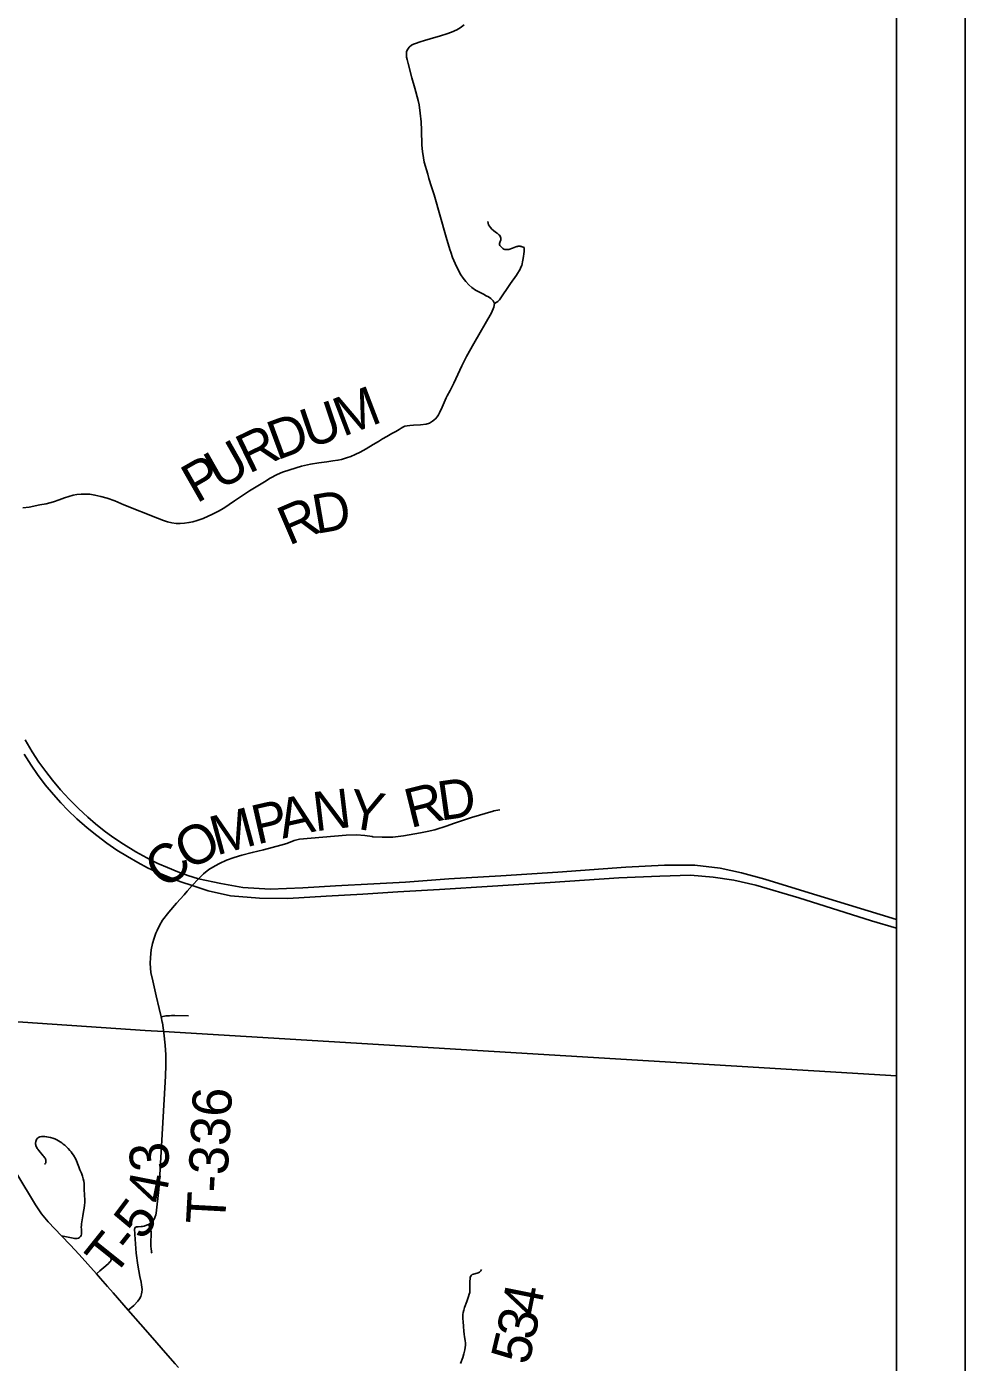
# Model space of a CAD drawing. Extents: x 0 to 34, y 0 to 22.
# Drawn here: x 7.513 to 8.876, y 18.32 to 20.26 of the extents above; entities that cross this region are included whole.
import ezdxf

# ---------------------------------------------------------------- set-up
doc = ezdxf.new("R2010")
doc.units = 0
for name, color, linetype in [('GM_X_County_Road', 7, 'Continuous'), ('GM_X_Township_Road', 7, 'Continuous'), ('GM_X_Township_Road_Text', 7, 'Continuous'), ('GM_X_Township_Text', 7, 'Continuous'), ('GM_X_US_Route', 7, 'Continuous'), ('SH_Data', 7, 'Continuous')]:
    doc.layers.add(name, color=color, linetype=linetype)

msp = doc.modelspace()

# ---------------------------------------------------------------- linework, layer by layer
at = {"layer": 'GM_X_County_Road'}
for points in [[(7.2732, 18.8224), (7.3172, 18.7836), (7.3241, 18.7776), (7.3413, 18.7644), (7.3454, 18.7613), (7.3763, 18.7385), (7.3883, 18.7285), (7.3995, 18.7177), (7.4162, 18.6992), (7.4726, 18.6329), (7.4803, 18.6227), (7.4832, 18.6185), (7.4987, 18.5942), (7.5258, 18.5488), (7.5346, 18.5361), (7.5444, 18.5242), (7.5636, 18.5039), (7.5761, 18.491), (7.5895, 18.477), (7.6144, 18.4487), (7.6202, 18.442), (7.6304, 18.4306), (7.6385, 18.4213), (7.6607, 18.396)], [(7.6607, 18.396), (7.6784, 18.3758), (7.6923, 18.3599), (7.7022, 18.3484), (7.7147, 18.334), (7.7289, 18.318), (7.7335, 18.3126)]]:
    msp.add_lwpolyline(points, dxfattribs=at)
at = {"layer": 'GM_X_Township_Road'}
for points in [[(7.5076, 19.5609), (7.5169, 19.5621), (7.5323, 19.5654), (7.5416, 19.5671), (7.5519, 19.5696), (7.5604, 19.5726), (7.568, 19.5756), (7.5741, 19.5777), (7.5806, 19.5795), (7.586, 19.5806), (7.5921, 19.581), (7.5985, 19.5811), (7.6047, 19.5807), (7.6123, 19.5797), (7.6209, 19.5777), (7.6299, 19.5751), (7.6411, 19.5711), (7.6544, 19.5656), (7.7032, 19.5459), (7.7119, 19.5425), (7.7178, 19.5407), (7.7239, 19.5394), (7.73, 19.5385), (7.7362, 19.5383), (7.7424, 19.5387), (7.7486, 19.5396), (7.7546, 19.5409), (7.7606, 19.5426), (7.7693, 19.5458), (7.7832, 19.5518), (7.7915, 19.5561), (7.7995, 19.5608), (7.8073, 19.5659), (7.8149, 19.5712), (7.8366, 19.5856), (7.8583, 19.599), (7.8667, 19.604), (7.8767, 19.6096), (7.8845, 19.6128), (7.8954, 19.6162), (7.9123, 19.6215), (7.9255, 19.6245), (7.9372, 19.6264), (7.9492, 19.6279), (7.9575, 19.6291), (7.965, 19.6302), (7.9701, 19.6314), (7.9776, 19.6336), (7.9838, 19.6358), (7.99, 19.6387), (7.9972, 19.642), (8.006, 19.6466), (8.0161, 19.6529), (8.0239, 19.6575), (8.0298, 19.6611), (8.0361, 19.6646), (8.0436, 19.669), (8.0492, 19.6721), (8.0542, 19.675), (8.0569, 19.6767), (8.0593, 19.6782), (8.0621, 19.6795), (8.0657, 19.6803), (8.0698, 19.6808), (8.0749, 19.6811), (8.0852, 19.6815), (8.0931, 19.6826), (8.0981, 19.6841), (8.1027, 19.6867), (8.1067, 19.6901), (8.1093, 19.6931), (8.1112, 19.6962), (8.1127, 19.699), (8.1137, 19.7014), (8.1152, 19.704), (8.1225, 19.7208), (8.1237, 19.7236), (8.128, 19.7313), (8.1334, 19.7423), (8.1449, 19.7672), (8.1517, 19.7808), (8.1626, 19.7995), (8.188, 19.8444), (8.1914, 19.8526), (8.1923, 19.8579), (8.1908, 19.8619), (8.1874, 19.8649), (8.1838, 19.8673), (8.1805, 19.8691), (8.1767, 19.8712), (8.1647, 19.8772), (8.1597, 19.8809), (8.1552, 19.8851), (8.151, 19.8896), (8.1472, 19.8945), (8.1437, 19.8996), (8.1392, 19.9076), (8.1352, 19.916), (8.1317, 19.9245), (8.1289, 19.9325), (8.1277, 19.9362), (8.1224, 19.954), (8.1048, 20.0155), (8.1029, 20.0215), (8.1009, 20.0271), (8.0972, 20.0394), (8.0957, 20.0454), (8.0905, 20.0632), (8.0892, 20.0692), (8.0878, 20.0784), (8.0872, 20.0877), (8.0865, 20.1094), (8.0859, 20.1218), (8.0848, 20.1342), (8.0829, 20.1465), (8.0817, 20.1526), (8.077, 20.1704), (8.0727, 20.1853), (8.0671, 20.2062), (8.0655, 20.2122), (8.0649, 20.2153), (8.0646, 20.2184), (8.0647, 20.2215), (8.0648, 20.2232), (8.0654, 20.2248), (8.0665, 20.2272), (8.0676, 20.2287), (8.0685, 20.2299), (8.0722, 20.2328), (8.0749, 20.2342), (8.0778, 20.2353), (8.0848, 20.2378), (8.0909, 20.2396), (8.0993, 20.2419), (8.114, 20.2465), (8.1231, 20.2493), (8.13, 20.2518), (8.1379, 20.2554), (8.1427, 20.2579), (8.1486, 20.2625)], [(8.2016, 19.9515), (8.2015, 19.9529), (8.2012, 19.9542), (8.2007, 19.9555), (8.1997, 19.9569), (8.1985, 19.9582), (8.1966, 19.9597), (8.1942, 19.9613), (8.1912, 19.9636), (8.1887, 19.9658), (8.1867, 19.9682), (8.1852, 19.97), (8.184, 19.9721), (8.1832, 19.9744), (8.1828, 19.9769)], [(8.1923, 19.8579), (8.1976, 19.8605), (8.1999, 19.8631), (8.2159, 19.8868), (8.2243, 19.8991), (8.2298, 19.9078), (8.231, 19.9104), (8.232, 19.913), (8.2327, 19.9156), (8.2333, 19.9185), (8.2337, 19.9207), (8.2347, 19.9262), (8.2352, 19.9299), (8.2354, 19.9333), (8.2356, 19.9391), (8.2328, 19.94), (8.2316, 19.9405), (8.2306, 19.9407), (8.2297, 19.9409), (8.229, 19.941), (8.2282, 19.9411), (8.2277, 19.9411), (8.2268, 19.941), (8.226, 19.9408), (8.2252, 19.9406), (8.2234, 19.94), (8.2188, 19.9381), (8.2172, 19.9375), (8.2149, 19.9366), (8.2135, 19.9363), (8.2122, 19.9361), (8.2108, 19.936), (8.2093, 19.9362), (8.2077, 19.9364), (8.2061, 19.9369), (8.2046, 19.9378), (8.2029, 19.9395), (8.2012, 19.9412), (8.2005, 19.9421), (8.2, 19.9434), (8.2, 19.9447), (8.2003, 19.9463), (8.2015, 19.9501), (8.2016, 19.9515)], [(8.1905, 19.1207), (8.1914, 19.1209), (8.2004, 19.1227)], [(8.1331, 19.1025), (8.1589, 19.1112), (8.1905, 19.1207)], [(7.7463, 19.0045), (7.7535, 19.0126), (7.7625, 19.0225), (7.77, 19.0298), (7.7775, 19.0357), (7.787, 19.0414), (7.793, 19.0446), (7.8035, 19.0496), (7.8142, 19.0534), (7.8256, 19.0569), (7.8406, 19.0604), (7.8568, 19.0644), (7.8824, 19.0711), (7.8907, 19.0738), (7.9014, 19.078), (7.9094, 19.0798), (7.9772, 19.0858), (7.9923, 19.0861), (8.004, 19.0851), (8.015, 19.0836), (8.0159, 19.0835)], [(8.0159, 19.0835), (8.0294, 19.0827), (8.045, 19.0831), (8.0606, 19.0848), (8.085, 19.0891), (8.0949, 19.0913)], [(8.0949, 19.0913), (8.1058, 19.0937), (8.1236, 19.0992), (8.1331, 19.1025)], [(7.7101, 18.8132), (7.7099, 18.8142), (7.7086, 18.822), (7.7056, 18.834), (7.7012, 18.8527), (7.6961, 18.8742), (7.6934, 18.8863), (7.6923, 18.8995), (7.6927, 18.9083), (7.6939, 18.9192), (7.6958, 18.9283), (7.6982, 18.9364), (7.7007, 18.9434), (7.7024, 18.9475), (7.706, 18.9547), (7.7105, 18.9623), (7.7195, 18.9738), (7.7307, 18.9871), (7.7418, 18.9993), (7.7463, 19.0045)], [(7.7058, 18.584), (7.7148, 18.7357), (7.7154, 18.7517), (7.7151, 18.7666), (7.7143, 18.7808), (7.7124, 18.7989), (7.7101, 18.8132)], [(7.7086, 18.822), (7.7134, 18.823), (7.7153, 18.8233), (7.7178, 18.8235), (7.7204, 18.8236), (7.7235, 18.8237), (7.7282, 18.8237), (7.7483, 18.8233)], [(7.5636, 18.5039), (7.5807, 18.5005), (7.5827, 18.5002), (7.5849, 18.5), (7.5865, 18.5002), (7.5882, 18.5006), (7.5898, 18.5016), (7.5911, 18.5032), (7.5922, 18.5046), (7.5927, 18.5063), (7.5929, 18.5084), (7.5928, 18.5107), (7.5926, 18.5138), (7.5924, 18.5167), (7.5925, 18.5189), (7.5929, 18.5213), (7.5934, 18.5244), (7.5945, 18.533), (7.5955, 18.5391), (7.5964, 18.5443), (7.597, 18.5486), (7.5973, 18.5523), (7.5973, 18.5554), (7.597, 18.5642), (7.5968, 18.5708), (7.5968, 18.5761), (7.5966, 18.5799), (7.596, 18.5834), (7.5952, 18.5869), (7.5941, 18.5907), (7.5925, 18.5948), (7.5904, 18.6), (7.5886, 18.6042), (7.5845, 18.6154), (7.5809, 18.6211), (7.5792, 18.6236), (7.5777, 18.6257), (7.5757, 18.6281), (7.5734, 18.6307), (7.5711, 18.6331), (7.5683, 18.6356), (7.5663, 18.6372), (7.5642, 18.639), (7.5619, 18.6405), (7.5595, 18.642), (7.5569, 18.6433), (7.5541, 18.6446), (7.5512, 18.6456), (7.5478, 18.6467), (7.5447, 18.6474), (7.5421, 18.6479), (7.5395, 18.6482), (7.5374, 18.6483), (7.5348, 18.6482), (7.5322, 18.6477), (7.5304, 18.6469), (7.5288, 18.6457), (7.5273, 18.6436), (7.5264, 18.6411), (7.526, 18.6384), (7.5261, 18.6372), (7.5262, 18.6361), (7.5265, 18.635), (7.527, 18.6338), (7.5276, 18.6324), (7.5285, 18.631), (7.5295, 18.6296), (7.5308, 18.628), (7.5372, 18.6201), (7.5381, 18.619), (7.5391, 18.6177), (7.5398, 18.6166), (7.5404, 18.6155), (7.5407, 18.6146), (7.5409, 18.614), (7.541, 18.6134), (7.5411, 18.6128), (7.5411, 18.6122), (7.5411, 18.6115), (7.541, 18.611), (7.5408, 18.6104), (7.5407, 18.6099), (7.5405, 18.6095), (7.5402, 18.6091), (7.5392, 18.6082)], [(7.67, 18.5144), (7.6701, 18.5151), (7.6702, 18.5157), (7.6704, 18.5159), (7.6706, 18.5161), (7.6709, 18.5163), (7.6714, 18.5166), (7.6725, 18.5168), (7.6748, 18.5171), (7.6793, 18.5175), (7.6813, 18.5177), (7.6837, 18.5182), (7.6873, 18.5193), (7.6902, 18.5205), (7.6931, 18.5225), (7.695, 18.5243), (7.6965, 18.5256), (7.6983, 18.528), (7.6994, 18.5306), (7.7006, 18.5343), (7.7011, 18.537), (7.705, 18.5711), (7.7058, 18.584)], [(7.6792, 18.4369), (7.6775, 18.4449), (7.6744, 18.4612), (7.6723, 18.479), (7.6711, 18.4924), (7.6702, 18.5059), (7.6702, 18.507), (7.6699, 18.5136), (7.67, 18.5144)], [(7.6949, 18.4788), (7.6946, 18.4804), (7.6942, 18.4823), (7.694, 18.4847), (7.6936, 18.4896), (7.6936, 18.4923), (7.6936, 18.4951), (7.694, 18.5057), (7.6939, 18.5078), (7.6938, 18.5098), (7.6936, 18.5113), (7.6933, 18.5129), (7.6928, 18.5144), (7.6902, 18.5205)], [(7.6144, 18.4487), (7.6193, 18.453), (7.6279, 18.4603), (7.6318, 18.4637), (7.6335, 18.4656), (7.6351, 18.4674), (7.6355, 18.4681), (7.6358, 18.4691), (7.6359, 18.4698), (7.6358, 18.4707), (7.6355, 18.4715), (7.635, 18.4726), (7.6344, 18.4736), (7.6333, 18.4749), (7.6324, 18.476), (7.6311, 18.4771), (7.6298, 18.4785), (7.6289, 18.4795), (7.6282, 18.4808), (7.6276, 18.4818), (7.6272, 18.4825), (7.6272, 18.484)], [(8.1738, 18.455), (8.1729, 18.4532), (8.1718, 18.452), (8.1706, 18.451), (8.169, 18.4502), (8.1673, 18.4496), (8.1622, 18.4482), (8.1603, 18.4476), (8.159, 18.4468), (8.158, 18.4455), (8.1574, 18.4439), (8.157, 18.4419), (8.1568, 18.4378), (8.1569, 18.4329), (8.1568, 18.4249), (8.1565, 18.4216), (8.1559, 18.4192), (8.1548, 18.4158), (8.1522, 18.4087), (8.149, 18.4001), (8.1478, 18.3961), (8.147, 18.3928), (8.1465, 18.3898), (8.1463, 18.3869), (8.1465, 18.3836), (8.1469, 18.3796), (8.1475, 18.3721), (8.148, 18.3653), (8.1484, 18.3612), (8.149, 18.3571), (8.1498, 18.3521), (8.1503, 18.3482), (8.1505, 18.3451), (8.1495, 18.3385), (8.1482, 18.3324), (8.1467, 18.3271), (8.1432, 18.3187)], [(7.6607, 18.396), (7.6688, 18.4026), (7.6747, 18.409), (7.6771, 18.4126), (7.6787, 18.416), (7.6798, 18.4195), (7.6805, 18.4223), (7.6808, 18.4258), (7.6805, 18.4294), (7.68, 18.4329), (7.6792, 18.4369)]]:
    msp.add_lwpolyline(points, dxfattribs=at)
at = {"layer": 'GM_X_Township_Text'}
msp.add_lwpolyline([(8.7763, 18.7365), (7.7116, 18.8006), (7.6851, 18.802), (7.2653, 18.8305), (6.9608, 18.8511), (6.9477, 18.852), (6.9018, 18.8551), (6.7713, 18.864), (6.3469, 18.8928), (5.4766, 18.9518), (4.3125, 19.0308), (4.2973, 19.0318), (4.1694, 19.0405), (3.3833, 19.0938), (3.2714, 17.3671), (3.2279, 16.6952), (3.1822, 15.9898), (3.1607, 15.6594), (3.1102, 14.8789), (3.0682, 14.2309), (3.0665, 14.2054)], dxfattribs=at)
at = {"layer": 'GM_X_US_Route'}
for points in [[(7.5109, 19.2242), (7.521, 19.207), (7.5309, 19.1919), (7.5408, 19.1783), (7.5507, 19.1656), (7.5624, 19.1517), (7.5749, 19.1379), (7.5881, 19.1246), (7.6017, 19.1119), (7.613, 19.1021), (7.6257, 19.092), (7.6382, 19.0828), (7.6538, 19.0725), (7.6718, 19.0615), (7.6876, 19.0528), (7.7038, 19.0447), (7.7174, 19.0386), (7.7324, 19.0325), (7.747, 19.0273), (7.7625, 19.0225), (7.7952, 19.0158), (7.8272, 19.01), (7.8667, 19.0074), (7.914, 19.0091), (7.9616, 19.0121), (8.0172, 19.0151), (8.0633, 19.0177), (8.1262, 19.0224), (8.2017, 19.0266), (8.2846, 19.0322), (8.3834, 19.0392), (8.4395, 19.0422), (8.4834, 19.0422), (8.5201, 19.0377), (8.5512, 19.0313), (8.5853, 19.0219), (8.6431, 19.0042), (8.7525, 18.9705), (8.7763, 18.9633)], [(7.5094, 19.2033), (7.5194, 19.1876), (7.5289, 19.1738), (7.5401, 19.159), (7.5519, 19.1446), (7.5627, 19.1326), (7.573, 19.1219), (7.586, 19.1095), (7.6009, 19.0964), (7.6149, 19.0851), (7.6293, 19.0743), (7.6441, 19.0642), (7.6593, 19.0546), (7.6744, 19.0459), (7.6887, 19.0385), (7.7043, 19.0311), (7.7209, 19.0241), (7.7371, 19.018), (7.7535, 19.0126), (7.7765, 19.0048), (7.8091, 18.9978), (7.8513, 18.9942), (7.8925, 18.9938), (7.9479, 18.9972), (8.0014, 19.0002), (8.052, 19.0036), (8.1128, 19.007), (8.1898, 19.0118), (8.2736, 19.017), (8.3729, 19.0239), (8.4326, 19.0263), (8.4772, 19.0275), (8.5103, 19.0249), (8.5403, 19.0204), (8.5721, 19.0134), (8.6344, 18.9949), (8.7399, 18.9616), (8.7763, 18.9507)]]:
    msp.add_lwpolyline(points, dxfattribs=at)
at = {"layer": 'SH_Data'}
for p, q in [((8.8763, 21.1054), (8.8763, 14.1054)), ((8.7763, 21.0054), (8.7763, 14.2054))]:
    msp.add_line(p, q, dxfattribs=at)

# ---------------------------------------------------------------- texts
at = {"layer": 'GM_X_Township_Road_Text'}
for s, height, rotation, p in [('M', 0.0568, 20.8873, (7.9724, 19.6639)), ('U', 0.0568, 18.7379, (7.9229, 19.6471)), ('D', 0.0568, 20.3267, (7.8764, 19.6298)), ('R', 0.0568, 25.7587, (7.8357, 19.6101)), ('U', 0.0568, 29.5217, (7.7931, 19.5859)), ('P', 0.0568, 29.7455, (7.7598, 19.5669)), ('R', 0.0568, 23.1945, (7.8938, 19.5057)), ('D', 0.0568, 9.8516, (7.9334, 19.5231)), ('D', 0.0568, 8.11, (8.1142, 19.1068)), ('A', 0.0568, 12.7074, (7.8849, 19.0805)), ('N', 0.0568, 6.8431, (7.9321, 19.0913)), ('Y', 0.0568, 350.8694, (7.9776, 19.0973)), ('R', 0.0568, 13.9548, (8.0704, 19.0958)), ('M', 0.0568, 15.1453, (7.7886, 19.0561)), ('P', 0.0568, 12.7963, (7.8475, 19.0721)), ('O', 0.0568, 28.0706, (7.7476, 19.0338)), ('C', 0.0568, 41.006, (7.7152, 19.0051)), ('T-336', 0.05682, 86.913, (7.8011, 18.5197)), ('3', 0.0568, 94.116, (7.7209, 18.5995)), ('4', 0.0568, 78.9309, (7.7132, 18.5488)), ('5', 0.0568, 53.1908, (7.6811, 18.4956)), ('T', 0.0568, 51.3496, (7.6388, 18.4426)), ('-', 0.0568, 51.4694, (7.6654, 18.4759)), ('4', 0.0568, 78.7444, (8.2575, 18.3855)), ('3', 0.0568, 78.2768, (8.2503, 18.3508)), ('5', 0.0568, 76.5583, (8.2417, 18.3149))]:
    msp.add_text(s, height=height, rotation=rotation, dxfattribs=at).set_placement(p)

doc.saveas('drawing.dxf')
